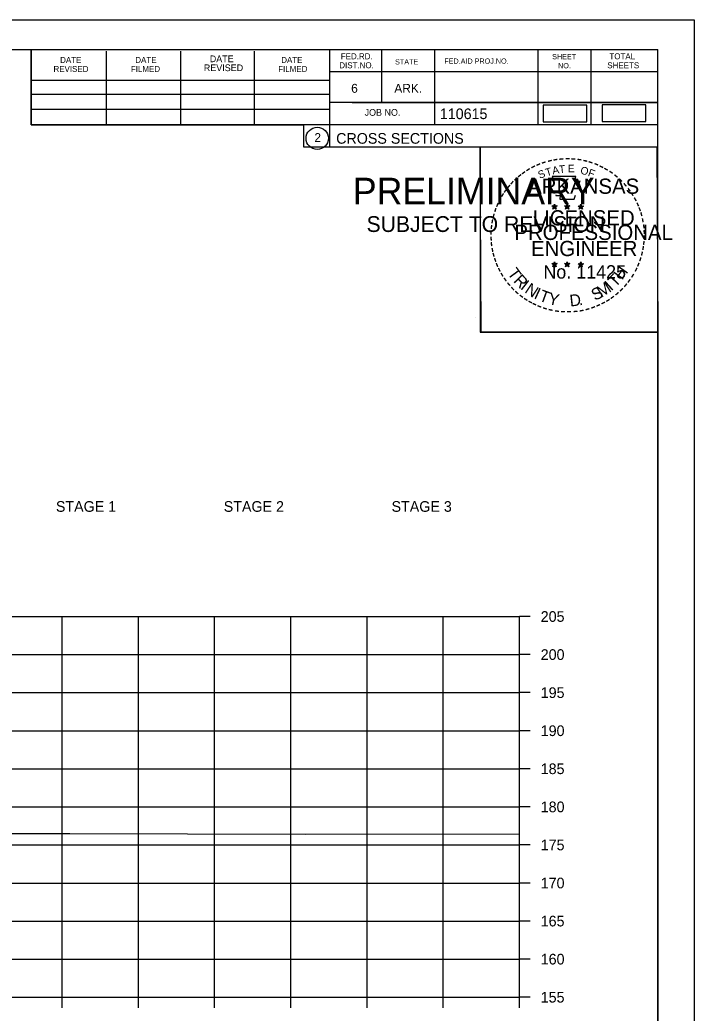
# Model space of a CAD drawing. Extents: x 1372132 to 1372465, y 380083 to 381790.
# Drawn here: x 1372376.4 to 1372464.9, y 381446.4 to 381576.9 of the extents above; entities that cross this region are included whole.
import ezdxf

# ---------------------------------------------------------------- set-up
doc = ezdxf.new("R2010")
doc.units = 0
for name, color, linetype in [('R_Axis', 7, 'Continuous'), ('R_Axis Annot', 7, 'Continuous'), ('R_Border', 7, 'Continuous'), ('R_Border PE', 7, 'Continuous'), ('R_Border Prem', 7, 'Continuous'), ('R_Erosion', 7, 'Continuous'), ('R_Exist Surface', 7, 'Continuous'), ('R_Grid', 7, 'Continuous'), ('R_No Plot', 7, 'Continuous')]:
    doc.layers.add(name, color=color, linetype=linetype)

msp = doc.modelspace()

# ---------------------------------------------------------------- linework, layer by layer
at = {"layer": 'R_Axis'}
for p, q in [((1372442.01, 381448.5), (1372442.01, 381498.5)), ((1372443.41, 381498.5), (1372442.01, 381498.5)), ((1372443.41, 381493.5), (1372442.01, 381493.5)), ((1372443.41, 381488.5), (1372442.01, 381488.5)), ((1372443.41, 381483.5), (1372442.01, 381483.5)), ((1372443.41, 381478.5), (1372442.01, 381478.5)), ((1372443.41, 381473.5), (1372442.01, 381473.5)), ((1372443.41, 381468.5), (1372442.01, 381468.5)), ((1372443.41, 381463.5), (1372442.01, 381463.5)), ((1372443.41, 381458.5), (1372442.01, 381458.5)), ((1372443.41, 381453.5), (1372442.01, 381453.5)), ((1372162.01, 381448.5), (1372442.01, 381448.5)), ((1372382.01, 381447.1), (1372382.01, 381448.5)), ((1372392.01, 381447.1), (1372392.01, 381448.5)), ((1372402.01, 381447.1), (1372402.01, 381448.5)), ((1372412.01, 381447.1), (1372412.01, 381448.5)), ((1372422.01, 381447.1), (1372422.01, 381448.5)), ((1372432.01, 381447.1), (1372432.01, 381448.5)), ((1372442.01, 381447.1), (1372442.01, 381448.5)), ((1372443.41, 381448.5), (1372442.01, 381448.5))]:
    msp.add_line(p, q, dxfattribs=at)
at = {"layer": 'R_Border'}
for p, q in [((1372144.01, 381572.96), (1372460.19, 381572.96)), ((1372377.93, 381563.08), (1372377.93, 381572.96)), ((1372417.09, 381572.96), (1372417.09, 381560.16)), ((1372423.93, 381572.96), (1372423.93, 381566.02)), ((1372430.87, 381572.96), (1372430.87, 381563.08)), ((1372444.45, 381572.96), (1372444.45, 381563.08)), ((1372451.39, 381572.96), (1372451.39, 381563.08)), ((1372460.19, 381367.5), (1372460.19, 381572.96)), ((1372387.79, 381563.08), (1372387.79, 381572.76)), ((1372397.55, 381563.08), (1372397.55, 381572.76)), ((1372407.23, 381563.08), (1372407.23, 381572.76)), ((1372377.93, 381568.94), (1372417.09, 381568.94)), ((1372460.19, 381570.02), (1372417.09, 381570.02)), ((1372460.19, 381570.04), (1372460.19, 381570.04)), ((1372377.93, 381567.08), (1372417.09, 381567.08)), ((1372377.93, 381563.08), (1372377.93, 381565.14)), ((1372377.93, 381565.14), (1372417.09, 381565.14)), ((1372460.19, 381566.02), (1372417.09, 381566.02)), ((1372420.05, 381566.02), (1372460.19, 381566.02)), ((1372460.19, 381563.08), (1372377.93, 381563.08)), ((1372417.09, 381560.16), (1372460.19, 381560.16))]:
    msp.add_line(p, q, dxfattribs=at)
msp.add_circle((1372415.48, 381561.3), 1.47, dxfattribs=at)
at = {"layer": 'R_Border PE'}
for p, q in [((1372446.28, 381552.42), (1372446.63, 381552.31)), ((1372446.28, 381552.42), (1372446.53, 381552.37)), ((1372446.28, 381552.42), (1372446.52, 381552.29)), ((1372446.41, 381552.01), (1372446.63, 381552.31)), ((1372446.41, 381552.01), (1372446.54, 381552.25)), ((1372446.41, 381552.01), (1372446.63, 381552.23)), ((1372446.63, 381552.67), (1372446.59, 381552.42)), ((1372446.63, 381552.31), (1372446.63, 381552.67)), ((1372446.63, 381552.67), (1372446.68, 381552.42)), ((1372446.98, 381552.42), (1372446.63, 381552.31)), ((1372446.84, 381552.01), (1372446.63, 381552.31)), ((1372446.84, 381552.01), (1372446.63, 381552.22)), ((1372446.98, 381552.42), (1372446.69, 381552.37)), ((1372446.84, 381552.01), (1372446.7, 381552.3)), ((1372446.98, 381552.42), (1372446.77, 381552.31)), ((1372447.95, 381552.42), (1372448.3, 381552.31)), ((1372447.95, 381552.42), (1372448.2, 381552.37)), ((1372447.95, 381552.42), (1372448.19, 381552.29)), ((1372448.08, 381552.01), (1372448.3, 381552.31)), ((1372448.08, 381552.01), (1372448.21, 381552.25)), ((1372448.08, 381552.01), (1372448.3, 381552.23)), ((1372448.3, 381552.67), (1372448.26, 381552.42)), ((1372448.3, 381552.31), (1372448.3, 381552.67)), ((1372448.3, 381552.67), (1372448.35, 381552.42)), ((1372448.65, 381552.42), (1372448.3, 381552.31)), ((1372448.51, 381552.01), (1372448.3, 381552.31)), ((1372448.51, 381552.01), (1372448.3, 381552.22)), ((1372448.65, 381552.42), (1372448.36, 381552.37)), ((1372448.51, 381552.01), (1372448.37, 381552.3)), ((1372448.65, 381552.42), (1372448.44, 381552.31)), ((1372449.71, 381552.4), (1372450.06, 381552.29)), ((1372449.71, 381552.4), (1372449.97, 381552.36)), ((1372449.71, 381552.4), (1372449.95, 381552.28)), ((1372449.85, 381552), (1372450.06, 381552.29)), ((1372449.85, 381552), (1372449.97, 381552.24)), ((1372449.85, 381552), (1372450.06, 381552.21)), ((1372450.06, 381552.66), (1372450.02, 381552.41)), ((1372450.06, 381552.29), (1372450.06, 381552.66)), ((1372450.06, 381552.66), (1372450.11, 381552.41)), ((1372450.41, 381552.4), (1372450.06, 381552.29)), ((1372450.28, 381552), (1372450.06, 381552.29)), ((1372450.28, 381552), (1372450.06, 381552.21)), ((1372450.41, 381552.4), (1372450.12, 381552.36)), ((1372450.28, 381552), (1372450.14, 381552.29)), ((1372450.41, 381552.4), (1372450.21, 381552.3)), ((1372446.28, 381544.84), (1372446.62, 381544.73)), ((1372446.28, 381544.84), (1372446.53, 381544.8)), ((1372446.28, 381544.84), (1372446.51, 381544.72)), ((1372446.41, 381544.44), (1372446.62, 381544.73)), ((1372446.41, 381544.44), (1372446.53, 381544.68)), ((1372446.41, 381544.44), (1372446.62, 381544.65)), ((1372446.62, 381545.1), (1372446.58, 381544.85)), ((1372446.62, 381544.73), (1372446.62, 381545.1)), ((1372446.62, 381545.1), (1372446.67, 381544.85)), ((1372446.97, 381544.84), (1372446.62, 381544.73)), ((1372446.84, 381544.44), (1372446.62, 381544.73)), ((1372446.84, 381544.44), (1372446.62, 381544.65)), ((1372446.97, 381544.84), (1372446.69, 381544.79)), ((1372446.84, 381544.44), (1372446.7, 381544.73)), ((1372446.97, 381544.84), (1372446.77, 381544.74)), ((1372447.94, 381544.84), (1372448.29, 381544.73)), ((1372447.94, 381544.84), (1372448.2, 381544.8)), ((1372447.94, 381544.84), (1372448.18, 381544.72)), ((1372448.08, 381544.44), (1372448.29, 381544.73)), ((1372448.08, 381544.44), (1372448.2, 381544.68)), ((1372448.08, 381544.44), (1372448.29, 381544.65)), ((1372448.29, 381545.1), (1372448.25, 381544.85)), ((1372448.29, 381544.73), (1372448.29, 381545.1)), ((1372448.29, 381545.1), (1372448.34, 381544.85)), ((1372448.64, 381544.84), (1372448.29, 381544.73)), ((1372448.51, 381544.44), (1372448.29, 381544.73)), ((1372448.51, 381544.44), (1372448.29, 381544.65)), ((1372448.64, 381544.84), (1372448.35, 381544.79)), ((1372448.51, 381544.44), (1372448.37, 381544.73)), ((1372448.64, 381544.84), (1372448.44, 381544.74)), ((1372449.71, 381544.83), (1372450.06, 381544.72)), ((1372449.71, 381544.83), (1372449.96, 381544.79)), ((1372449.71, 381544.83), (1372449.95, 381544.71)), ((1372449.84, 381544.43), (1372450.06, 381544.72)), ((1372449.84, 381544.43), (1372449.97, 381544.67)), ((1372449.84, 381544.43), (1372450.06, 381544.64)), ((1372450.06, 381545.09), (1372450.02, 381544.84)), ((1372450.06, 381544.72), (1372450.06, 381545.09)), ((1372450.06, 381545.09), (1372450.11, 381544.84)), ((1372450.41, 381544.83), (1372450.06, 381544.72)), ((1372450.27, 381544.43), (1372450.06, 381544.72)), ((1372450.27, 381544.43), (1372450.06, 381544.64)), ((1372450.41, 381544.83), (1372450.12, 381544.78)), ((1372450.27, 381544.43), (1372450.14, 381544.72)), ((1372450.41, 381544.83), (1372450.2, 381544.73))]:
    msp.add_line(p, q, dxfattribs=at)
for points in [[(1372446.32, 381556.29), (1372446.59, 381555.47)], [(1372449.83, 381555.37), (1372449.97, 381555.66), (1372449.29, 381555.63), (1372449.44, 381556.29), (1372446.32, 381556.29)], [(1372446.81, 381553.87), (1372446.81, 381553.78), (1372447.38, 381553.77), (1372447.32, 381553.29), (1372449.19, 381553.29), (1372449.39, 381553.83)], [(1372446.63, 381552.67), (1372446.84, 381552.01), (1372446.28, 381552.42), (1372446.98, 381552.42), (1372446.41, 381552.01), (1372446.63, 381552.67)], [(1372448.3, 381552.67), (1372448.51, 381552.01), (1372447.95, 381552.42), (1372448.65, 381552.42), (1372448.08, 381552.01), (1372448.3, 381552.67)], [(1372450.06, 381552.66), (1372450.28, 381552), (1372449.71, 381552.4), (1372450.41, 381552.4), (1372449.85, 381552), (1372450.06, 381552.66)], [(1372446.62, 381545.1), (1372446.84, 381544.44), (1372446.28, 381544.84), (1372446.97, 381544.84), (1372446.41, 381544.44), (1372446.62, 381545.1)], [(1372448.29, 381545.1), (1372448.51, 381544.44), (1372447.94, 381544.84), (1372448.64, 381544.84), (1372448.08, 381544.44), (1372448.29, 381545.1)], [(1372450.06, 381545.09), (1372450.27, 381544.43), (1372449.71, 381544.83), (1372450.41, 381544.83), (1372449.84, 381544.43), (1372450.06, 381545.09)]]:
    msp.add_lwpolyline(points, dxfattribs=at)
for centre, radius in [((1372446.63, 381552.3), 0.172), ((1372446.63, 381552.3), 0.145), ((1372446.63, 381552.3), 0.116), ((1372446.63, 381552.3), 0.0991), ((1372446.63, 381552.3), 0.0747), ((1372446.63, 381552.3), 0.0495), ((1372446.63, 381552.3), 0.0296), ((1372448.3, 381552.3), 0.172), ((1372448.3, 381552.3), 0.145), ((1372448.3, 381552.3), 0.116), ((1372448.3, 381552.3), 0.0991), ((1372448.3, 381552.3), 0.0747), ((1372448.3, 381552.3), 0.0495), ((1372448.3, 381552.3), 0.0296), ((1372450.06, 381552.29), 0.172), ((1372450.06, 381552.29), 0.145), ((1372450.06, 381552.29), 0.116), ((1372450.06, 381552.29), 0.0991), ((1372450.06, 381552.29), 0.0747), ((1372450.06, 381552.29), 0.0495), ((1372450.06, 381552.29), 0.0296), ((1372446.62, 381544.73), 0.172), ((1372446.62, 381544.73), 0.145), ((1372446.62, 381544.73), 0.116), ((1372446.62, 381544.73), 0.0991), ((1372446.62, 381544.73), 0.0747), ((1372446.62, 381544.73), 0.0495), ((1372446.62, 381544.73), 0.0296), ((1372448.29, 381544.73), 0.172), ((1372448.29, 381544.73), 0.145), ((1372448.29, 381544.73), 0.116), ((1372448.29, 381544.73), 0.0991), ((1372448.29, 381544.73), 0.0747), ((1372448.29, 381544.73), 0.0495), ((1372448.29, 381544.73), 0.0296), ((1372450.06, 381544.72), 0.172), ((1372450.06, 381544.72), 0.145), ((1372450.06, 381544.72), 0.116), ((1372450.06, 381544.72), 0.0991), ((1372450.06, 381544.72), 0.0747), ((1372450.06, 381544.72), 0.0495), ((1372450.06, 381544.72), 0.0296)]:
    msp.add_circle(centre, radius, dxfattribs=at)
at = {"layer": 'R_Erosion'}
for points in [[(1372445.13, 381563.46), (1372450.85, 381563.46), (1372450.85, 381565.64), (1372445.13, 381565.64)], [(1372452.88, 381563.52), (1372458.59, 381563.52), (1372458.59, 381565.7), (1372452.88, 381565.7)]]:
    msp.add_lwpolyline(points, close=True, dxfattribs=at)
at = {"layer": 'R_Exist Surface'}
msp.add_lwpolyline([(1372312.02, 381474.39), (1372315.9, 381473.71), (1372319.55, 381473.06), (1372327.85, 381470.33), (1372334.58, 381468.14), (1372337.02, 381468.17), (1372340.31, 381468.17), (1372345.08, 381469), (1372350.75, 381470.01), (1372382.98, 381469.99), (1372413.87, 381469.93), (1372442.01, 381469.98)], dxfattribs=at)
at = {"layer": 'R_Grid'}
for p, q in [((1372162.01, 381498.5), (1372442.01, 381498.5)), ((1372382.01, 381448.5), (1372382.01, 381498.5)), ((1372392.01, 381448.5), (1372392.01, 381498.5)), ((1372402.01, 381448.5), (1372402.01, 381498.5)), ((1372412.01, 381448.5), (1372412.01, 381498.5)), ((1372422.01, 381448.5), (1372422.01, 381498.5)), ((1372432.01, 381448.5), (1372432.01, 381498.5)), ((1372442.01, 381448.5), (1372442.01, 381498.5)), ((1372162.01, 381493.5), (1372442.01, 381493.5)), ((1372162.01, 381488.5), (1372442.01, 381488.5)), ((1372162.01, 381483.5), (1372442.01, 381483.5)), ((1372162.01, 381478.5), (1372442.01, 381478.5)), ((1372162.01, 381473.5), (1372442.01, 381473.5)), ((1372162.01, 381468.5), (1372442.01, 381468.5)), ((1372162.01, 381463.5), (1372442.01, 381463.5)), ((1372162.01, 381458.5), (1372442.01, 381458.5)), ((1372162.01, 381453.5), (1372442.01, 381453.5)), ((1372162.01, 381448.5), (1372442.01, 381448.5))]:
    msp.add_line(p, q, dxfattribs=at)
at = {"layer": 'R_No Plot'}
for p, q in [((1372131.61, 381576.86), (1372464.95, 381576.86)), ((1372436.23, 381537.71), (1372436.23, 381537.71))]:
    msp.add_line(p, q, dxfattribs=at)
for points in [[(1372131.61, 381576.86), (1372464.95, 381576.86), (1372464.95, 381363.52), (1372131.61, 381363.52)], [(1372377.93, 381572.96), (1372377.93, 381563.08), (1372413.67, 381563.08), (1372413.67, 381560.16), (1372436.87, 381560.16), (1372436.87, 381535.83), (1372460.19, 381535.83), (1372460.19, 381367.5), (1372144.01, 381367.5), (1372144.01, 381572.96)], [(1372436.87, 381560.16), (1372460.07, 381560.16), (1372460.19, 381535.83), (1372436.99, 381535.83)]]:
    msp.add_lwpolyline(points, close=True, dxfattribs=at)

# ---------------------------------------------------------------- texts
at = {"layer": 'R_Axis Annot'}
for s, p in [('STAGE 1', (1372381.17, 381512.25)), ('STAGE 2', (1372403.2, 381512.25)), ('STAGE 3', (1372425.23, 381512.25)), ('205', (1372444.81, 381497.8)), ('200', (1372444.81, 381492.8)), ('195', (1372444.81, 381487.8)), ('190', (1372444.81, 381482.8)), ('185', (1372444.81, 381477.8)), ('180', (1372444.81, 381472.8)), ('175', (1372444.81, 381467.8)), ('170', (1372444.81, 381462.8)), ('165', (1372444.81, 381457.8)), ('160', (1372444.81, 381452.8)), ('155', (1372444.81, 381447.8))]:
    msp.add_text(s, height=1.4, dxfattribs=at).set_placement(p)
at = {"layer": 'R_Border'}
for s, height, p in [('DATE', 0.782, (1372381.73, 381571.2)), ('DATE', 0.782, (1372391.59, 381571.2)), ('DATE', 0.879, (1372401.37, 381571.3)), ('DATE', 0.782, (1372410.75, 381571.2)), ('FED.RD.', 0.782, (1372418.57, 381571.68)), ('STATE', 0.684, (1372425.69, 381571)), ('FED.AID PROJ.NO.', 0.684, (1372432.15, 381571.1)), ('SHEET', 0.684, (1372446.31, 381571.68)), ('TOTAL', 0.782, (1372453.83, 381571.68)), ('REVISED', 0.782, (1372380.85, 381570.02)), ('FILMED', 0.782, (1372391.01, 381570.02)), ('REVISED', 0.879, (1372400.59, 381570.12)), ('FILMED', 0.782, (1372410.35, 381570.02)), ('DIST.NO.', 0.782, (1372418.37, 381570.5)), ('NO.', 0.684, (1372447.09, 381570.5)), ('SHEETS', 0.782, (1372453.55, 381570.5)), ('6', 1.17, (1372419.93, 381567.28)), ('ARK.', 1.172, (1372425.59, 381567.28)), ('JOB NO.', 0.879, (1372421.69, 381564.26)), ('110615', 1.4, (1372431.57, 381563.82)), ('2', 1.17, (1372415.1, 381560.81)), ('CROSS SECTIONS', 1.4, (1372417.96, 381560.59))]:
    msp.add_text(s, height=height, rotation=360, dxfattribs=at).set_placement(p)
at = {"layer": 'R_Border PE'}
for s, height, rotation, p in [('-', 1.6, 13.6301, (1372445.82, 381557.66)), ('-', 1.6, 10.2193, (1372446.5, 381557.82)), ('-', 1.6, 5.8968, (1372447.23, 381557.93)), ('-', 1.6, 0.1862, (1372448, 381558.01)), ('-', 1.6, 357.743, (1372448.72, 381557.99)), ('-', 1.6, 352.1617, (1372449.46, 381557.94)), ('-', 1.6, 347.2049, (1372450.18, 381557.82)), ('-', 1.6, 34.0636, (1372443.2, 381556.47)), ('-', 1.6, 28.7918, (1372443.8, 381556.84)), ('-', 1.6, 24.3072, (1372444.43, 381557.15)), ('-', 1.6, 19.1761, (1372445.07, 381557.42)), ('T', 1, 16.4036, (1372445.59, 381556.3)), ('A', 1, 11.2132, (1372446.42, 381556.55)), ('T', 1, 6.0228, (1372447.26, 381556.72)), ('E', 1, 0.8323, (1372448.37, 381556.83)), ('O', 1, 350.4515, (1372449.97, 381556.62)), ('F', 1, 340.0707, (1372450.93, 381556.39)), ('-', 1.6, 342.3362, (1372450.82, 381557.67)), ('-', 1.6, 337.8551, (1372451.55, 381557.45)), ('-', 1.6, 334.1211, (1372452.18, 381557.17)), ('-', 1.6, 329.6409, (1372452.76, 381556.89)), ('-', 1.6, 42.9622, (1372441.72, 381555.28)), ('-', 1.6, 38.9507, (1372442.15, 381555.69)), ('-', 1.6, 36.2317, (1372442.63, 381556.07)), ('ARKANSAS', 2, 360, (1372443.17, 381554.01)), ('S', 1, 21.594, (1372444.68, 381555.97)), ('-', 1.6, 325.8627, (1372453.41, 381556.53)), ('-', 1.6, 320.5297, (1372454.02, 381556.1)), ('-', 1.6, 315.5786, (1372454.62, 381555.62)), ('-', 1.6, 54.2325, (1372440.45, 381553.74)), ('-', 1.6, 50.6142, (1372440.87, 381554.31)), ('-', 1.6, 48.423, (1372441.27, 381554.8)), ('-', 1.6, 309.8797, (1372455.18, 381555.07)), ('-', 1.6, 306.6522, (1372455.71, 381554.46)), ('-', 1.6, 62.8713, (1372439.82, 381552.6)), ('-', 1.6, 58.0706, (1372440.13, 381553.22)), ('-', 1.4, 303.6753, (1372456.2, 381553.9)), ('-', 1.6, 299.6684, (1372456.51, 381553.29)), ('-', 1.6, 72.3945, (1372439.34, 381551.36)), ('-', 1.6, 67.7743, (1372439.56, 381551.99)), ('DWB', 0.01, 360, (1372446.62, 381552.3)), ('DWB', 0.01, 360, (1372448.29, 381552.3)), ('DWB', 0.01, 360, (1372450.05, 381552.29)), ('-', 1.6, 294.6628, (1372456.84, 381552.68)), ('-', 1.6, 290.5728, (1372457.1, 381552.1)), ('-', 1.6, 75.461, (1372439.14, 381550.65)), ('LICENSED', 2, 360, (1372443.77, 381549.86)), ('-', 1.6, 285.1233, (1372457.33, 381551.52)), ('-', 1.6, 280.5493, (1372457.53, 381550.78)), ('-', 1.6, 85.1863, (1372438.93, 381549.24)), ('-', 1.6, 81.2013, (1372439.01, 381549.94)), ('PROFESSIONAL', 2, 360, (1372441.35, 381547.95)), ('-', 1.6, 276.5962, (1372457.69, 381550.01)), ('-', 1.6, 94.1959, (1372438.94, 381547.82)), ('-', 1.6, 89.0622, (1372438.91, 381548.54)), ('-', 1.6, 274.3301, (1372457.75, 381549.29)), ('-', 1.6, 269.9407, (1372457.79, 381548.66)), ('-', 1.6, 98.9479, (1372439.01, 381547.15)), ('-', 1.6, 101.7149, (1372439.15, 381546.42)), ('ENGINEER', 2, 360, (1372443.53, 381545.83)), ('-', 1.6, 260.9953, (1372457.7, 381547.34)), ('-', 1.6, 263.5172, (1372457.77, 381547.99)), ('-', 1.6, 105.4578, (1372439.31, 381545.82)), ('-', 1.6, 109.0874, (1372439.53, 381545.19)), ('-', 1.6, 252.8681, (1372457.4, 381545.94)), ('-', 1.6, 255.7626, (1372457.59, 381546.66)), ('-', 1.6, 114.0643, (1372439.78, 381544.6)), ('-', 1.6, 115.7289, (1372440.09, 381543.98)), ('T', 1.54, 306.0406, (1372440.38, 381543.57)), ('No. 11425', 1.757, 360, (1372445.16, 381542.88)), ('DWB', 0.01, 360, (1372446.61, 381544.73)), ('DWB', 0.01, 360, (1372448.28, 381544.73)), ('DWB', 0.01, 360, (1372450.05, 381544.72)), ('H', 1.54, 54.6088, (1372455.5, 381542.61)), ('-', 1.6, 244.6197, (1372456.92, 381544.64)), ('-', 1.6, 247.8887, (1372457.18, 381545.27)), ('-', 1.6, 120.4471, (1372440.44, 381543.39)), ('-', 1.6, 125.8934, (1372440.85, 381542.83)), ('R', 1.54, 314.005, (1372441.15, 381542.52)), ('T', 1.54, 46.6444, (1372454.61, 381541.66)), ('-', 1.6, 233.8452, (1372456.12, 381543.23)), ('-', 1.6, 239.0712, (1372456.53, 381543.88)), ('-', 1.6, 130.7181, (1372441.31, 381542.28)), ('-', 1.6, 134.2238, (1372441.82, 381541.73)), ('I', 1.54, 321.9694, (1372442.05, 381541.59)), ('N', 1.54, 326.5002, (1372442.61, 381541.12)), ('I', 1.54, 335.3603, (1372443.82, 381540.33)), ('S', 1.54, 26.9312, (1372451.93, 381539.93)), ('M', 1.54, 32.6563, (1372452.77, 381540.34)), ('I', 1.54, 42.1136, (1372454.05, 381541.19)), ('-', 1.6, 225.7653, (1372455.21, 381542.1)), ('-', 1.6, 231.2538, (1372455.69, 381542.67)), ('-', 1.6, 138.9338, (1372442.35, 381541.27)), ('-', 1.6, 144.6463, (1372442.91, 381540.86)), ('-', 1.6, 148.0898, (1372443.47, 381540.49)), ('T', 1.54, 339.8912, (1372444.48, 381540.01)), ('Y', 1.54, 347.8556, (1372445.7, 381539.56)), ('D', 1.54, 6.3969, (1372448.69, 381539.2)), ('-', 1.6, 212.2491, (1372453.61, 381540.73)), ('-', 1.6, 215.7363, (1372454.14, 381541.12)), ('-', 1.6, 221.0851, (1372454.69, 381541.59)), ('-', 1.6, 151.5704, (1372444.05, 381540.17)), ('-', 1.6, 154.6002, (1372444.57, 381539.92)), ('-', 1.6, 158.5612, (1372445.19, 381539.67)), ('-', 1.6, 162.7983, (1372445.88, 381539.45)), ('.', 1.54, 13.7642, (1372449.88, 381539.33)), ('-', 1.6, 195.4743, (1372451.13, 381539.55)), ('-', 1.6, 200.7184, (1372451.81, 381539.8)), ('-', 1.6, 204.2516, (1372452.43, 381540.07)), ('-', 1.6, 207.3568, (1372453.05, 381540.39)), ('-', 1.6, 167.5555, (1372446.59, 381539.29)), ('-', 1.6, 173.1155, (1372447.37, 381539.18)), ('-', 1.6, 176.5183, (1372448.11, 381539.13)), ('-', 1.6, 181.5918, (1372448.86, 381539.15)), ('-', 1.6, 185.8167, (1372449.67, 381539.22)), ('-', 1.6, 191.2858, (1372450.4, 381539.35))]:
    msp.add_text(s, height=height, rotation=rotation, dxfattribs=at).set_placement(p)
at = {"layer": 'R_Border Prem'}
for s, height, p in [('PRELIMINARY', 3.5, (1372420.15, 381552.62)), ('DWB', 0.01, (1372420.89, 381554.47)), ('SUBJECT TO REVISION', 2.0751, (1372421.95, 381549))]:
    msp.add_text(s, height=height, rotation=360, dxfattribs=at).set_placement(p)

doc.saveas('drawing.dxf')
